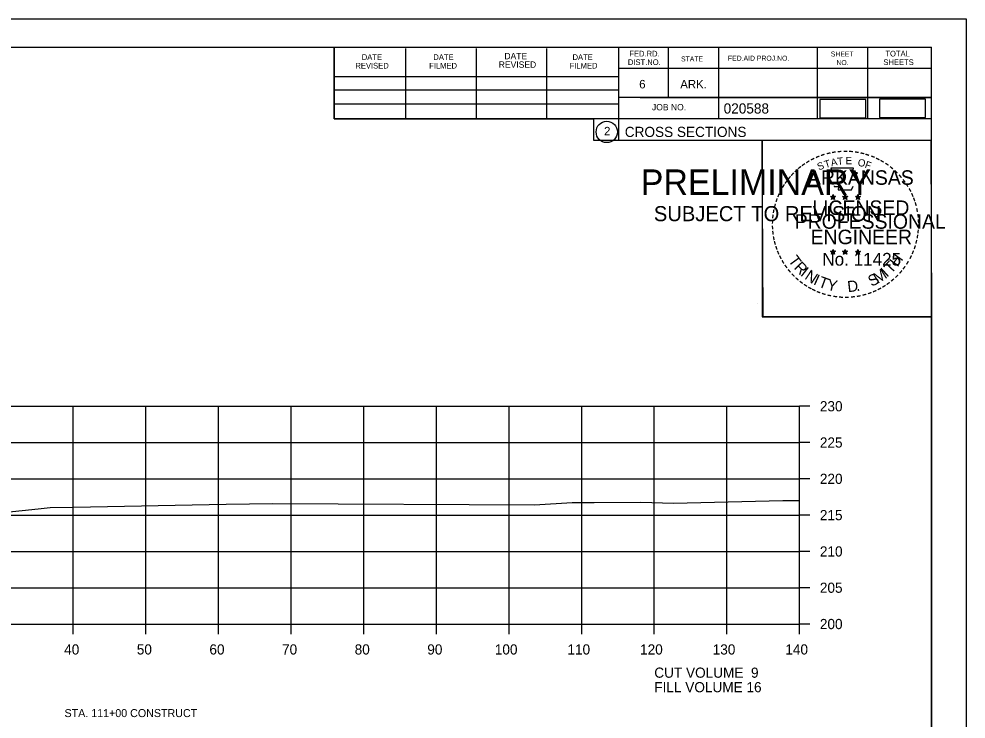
# Model space of a CAD drawing. Extents: x 1368968 to 1369915, y 377395 to 380381.
# Drawn here: x 1369784.3 to 1369914.7, y 377511.6 to 377608 of the extents above; entities that cross this region are included whole.
import ezdxf

# ---------------------------------------------------------------- set-up
doc = ezdxf.new("R2010")
doc.units = 0
for name, color, linetype in [('Default', 7, 'Continuous'), ('S_BREAKLINE_ANNOT', 7, 'Continuous'), ('S_BRIDGE', 7, 'Continuous'), ('S_BRIDGE_ANNOT', 7, 'Continuous'), ('S_BUILDING_ANNOT', 7, 'Continuous'), ('S_CAL_CORNER', 7, 'Continuous'), ('S_CTL_TABLE', 7, 'Continuous'), ('S_DITCHLINE_ANNOT', 7, 'Continuous'), ('S_DROP_INLET', 7, 'Continuous')]:
    doc.layers.add(name, color=color, linetype=linetype)

msp = doc.modelspace()

# ---------------------------------------------------------------- linework, layer by layer
at = {"layer": 'Default'}
for points in [[(1369894.57, 377594.42), (1369900.91, 377594.42), (1369900.91, 377596.94), (1369894.57, 377596.94)], [(1369902.8, 377594.46), (1369909.14, 377594.46), (1369909.14, 377596.98), (1369902.8, 377596.98)]]:
    msp.add_lwpolyline(points, close=True, dxfattribs=at)
at = {"layer": 'S_BREAKLINE_ANNOT'}
for p, q in [((1369891.78, 377524.68), (1369891.78, 377554.68)), ((1369893.18, 377554.68), (1369891.78, 377554.68)), ((1369893.18, 377549.68), (1369891.78, 377549.68)), ((1369893.18, 377544.68), (1369891.78, 377544.68)), ((1369893.18, 377539.68), (1369891.78, 377539.68)), ((1369893.18, 377534.68), (1369891.78, 377534.68)), ((1369893.18, 377529.68), (1369891.78, 377529.68)), ((1369611.78, 377524.68), (1369891.78, 377524.68)), ((1369791.78, 377523.28), (1369791.78, 377524.68)), ((1369801.78, 377523.28), (1369801.78, 377524.68)), ((1369811.78, 377523.28), (1369811.78, 377524.68)), ((1369821.78, 377523.28), (1369821.78, 377524.68)), ((1369831.78, 377523.28), (1369831.78, 377524.68)), ((1369841.78, 377523.28), (1369841.78, 377524.68)), ((1369851.78, 377523.28), (1369851.78, 377524.68)), ((1369861.78, 377523.28), (1369861.78, 377524.68)), ((1369871.78, 377523.28), (1369871.78, 377524.68)), ((1369881.78, 377523.28), (1369881.78, 377524.68)), ((1369891.78, 377523.28), (1369891.78, 377524.68)), ((1369893.18, 377524.68), (1369891.78, 377524.68))]:
    msp.add_line(p, q, dxfattribs=at)
at = {"layer": 'S_BRIDGE_ANNOT'}
for p, q in [((1369593.78, 377604.14), (1369909.96, 377604.14)), ((1369827.7, 377594.26), (1369827.7, 377604.14)), ((1369837.56, 377594.26), (1369837.56, 377603.94)), ((1369847.32, 377594.26), (1369847.32, 377603.94)), ((1369857, 377594.26), (1369857, 377603.94)), ((1369866.86, 377604.14), (1369866.86, 377591.34)), ((1369873.7, 377604.14), (1369873.7, 377597.2)), ((1369880.64, 377604.14), (1369880.64, 377594.26)), ((1369894.22, 377604.14), (1369894.22, 377594.26)), ((1369901.16, 377604.14), (1369901.16, 377594.26)), ((1369909.96, 377398.68), (1369909.96, 377604.14)), ((1369909.96, 377601.22), (1369909.96, 377601.22)), ((1369827.7, 377600.12), (1369866.86, 377600.12)), ((1369909.96, 377601.2), (1369866.86, 377601.2)), ((1369827.7, 377598.26), (1369866.86, 377598.26)), ((1369827.7, 377594.26), (1369827.7, 377596.32)), ((1369827.7, 377596.32), (1369866.86, 377596.32)), ((1369909.96, 377597.2), (1369866.86, 377597.2)), ((1369869.82, 377597.2), (1369909.96, 377597.2)), ((1369909.96, 377594.26), (1369827.7, 377594.26)), ((1369866.86, 377591.34), (1369909.96, 377591.34))]:
    msp.add_line(p, q, dxfattribs=at)
msp.add_circle((1369865.24, 377592.47), 1.47, dxfattribs=at)
at = {"layer": 'S_BUILDING_ANNOT'}
for p, q in [((1369896.04, 377583.59), (1369896.39, 377583.48)), ((1369896.04, 377583.59), (1369896.29, 377583.55)), ((1369896.04, 377583.59), (1369896.28, 377583.47)), ((1369896.17, 377583.18), (1369896.39, 377583.48)), ((1369896.17, 377583.18), (1369896.3, 377583.43)), ((1369896.17, 377583.18), (1369896.39, 377583.4)), ((1369896.39, 377583.85), (1369896.35, 377583.59)), ((1369896.39, 377583.48), (1369896.39, 377583.85)), ((1369896.39, 377583.85), (1369896.44, 377583.6)), ((1369896.74, 377583.59), (1369896.39, 377583.48)), ((1369896.6, 377583.18), (1369896.39, 377583.48)), ((1369896.6, 377583.18), (1369896.39, 377583.4)), ((1369896.74, 377583.59), (1369896.45, 377583.54)), ((1369896.6, 377583.18), (1369896.47, 377583.48)), ((1369896.74, 377583.59), (1369896.53, 377583.49)), ((1369897.71, 377583.59), (1369898.06, 377583.48)), ((1369897.71, 377583.59), (1369897.96, 377583.55)), ((1369897.71, 377583.59), (1369897.95, 377583.47)), ((1369897.84, 377583.18), (1369898.06, 377583.48)), ((1369897.84, 377583.18), (1369897.97, 377583.43)), ((1369897.84, 377583.18), (1369898.06, 377583.4)), ((1369898.06, 377583.85), (1369898.02, 377583.59)), ((1369898.06, 377583.48), (1369898.06, 377583.85)), ((1369898.06, 377583.85), (1369898.11, 377583.6)), ((1369898.41, 377583.59), (1369898.06, 377583.48)), ((1369898.27, 377583.18), (1369898.06, 377583.48)), ((1369898.27, 377583.18), (1369898.06, 377583.4)), ((1369898.41, 377583.59), (1369898.12, 377583.54)), ((1369898.27, 377583.18), (1369898.14, 377583.48)), ((1369898.41, 377583.59), (1369898.2, 377583.49)), ((1369899.48, 377583.58), (1369899.82, 377583.47)), ((1369899.48, 377583.58), (1369899.73, 377583.54)), ((1369899.48, 377583.58), (1369899.71, 377583.46)), ((1369899.61, 377583.17), (1369899.82, 377583.47)), ((1369899.61, 377583.17), (1369899.73, 377583.42)), ((1369899.61, 377583.17), (1369899.82, 377583.39)), ((1369899.82, 377583.83), (1369899.78, 377583.58)), ((1369899.82, 377583.47), (1369899.82, 377583.83)), ((1369899.82, 377583.83), (1369899.87, 377583.58)), ((1369900.17, 377583.58), (1369899.82, 377583.47)), ((1369900.04, 377583.17), (1369899.82, 377583.47)), ((1369900.04, 377583.17), (1369899.82, 377583.39)), ((1369900.17, 377583.58), (1369899.89, 377583.53)), ((1369900.04, 377583.17), (1369899.9, 377583.46)), ((1369900.17, 377583.58), (1369899.97, 377583.48)), ((1369896.04, 377576.02), (1369896.39, 377575.91)), ((1369896.04, 377576.02), (1369896.29, 377575.97)), ((1369896.04, 377576.02), (1369896.27, 377575.9)), ((1369896.17, 377575.61), (1369896.39, 377575.91)), ((1369896.17, 377575.61), (1369896.3, 377575.86)), ((1369896.17, 377575.61), (1369896.38, 377575.83)), ((1369896.39, 377576.27), (1369896.35, 377576.02)), ((1369896.6, 377575.61), (1369896.38, 377575.83)), ((1369896.39, 377575.91), (1369896.39, 377576.27)), ((1369896.39, 377576.27), (1369896.44, 377576.02)), ((1369896.73, 377576.02), (1369896.39, 377575.91)), ((1369896.6, 377575.61), (1369896.39, 377575.91)), ((1369896.73, 377576.02), (1369896.45, 377575.97)), ((1369896.6, 377575.61), (1369896.46, 377575.9)), ((1369896.73, 377576.02), (1369896.53, 377575.92)), ((1369897.71, 377576.02), (1369898.06, 377575.91)), ((1369897.71, 377576.02), (1369897.96, 377575.97)), ((1369897.71, 377576.02), (1369897.94, 377575.9)), ((1369897.84, 377575.61), (1369898.06, 377575.91)), ((1369897.84, 377575.61), (1369897.97, 377575.86)), ((1369897.84, 377575.61), (1369898.05, 377575.83)), ((1369898.06, 377576.27), (1369898.01, 377576.02)), ((1369898.27, 377575.61), (1369898.05, 377575.83)), ((1369898.06, 377575.91), (1369898.06, 377576.27)), ((1369898.06, 377576.27), (1369898.1, 377576.02)), ((1369898.4, 377576.02), (1369898.06, 377575.91)), ((1369898.27, 377575.61), (1369898.06, 377575.91)), ((1369898.4, 377576.02), (1369898.12, 377575.97)), ((1369898.27, 377575.61), (1369898.13, 377575.9)), ((1369898.4, 377576.02), (1369898.2, 377575.92)), ((1369899.47, 377576.01), (1369899.82, 377575.9)), ((1369899.47, 377576.01), (1369899.73, 377575.96)), ((1369899.47, 377576.01), (1369899.71, 377575.89)), ((1369899.61, 377575.6), (1369899.82, 377575.9)), ((1369899.61, 377575.6), (1369899.73, 377575.85)), ((1369899.61, 377575.6), (1369899.82, 377575.82)), ((1369899.82, 377576.26), (1369899.78, 377576.01)), ((1369899.82, 377575.9), (1369899.82, 377576.26)), ((1369899.82, 377576.26), (1369899.87, 377576.01)), ((1369900.17, 377576.01), (1369899.82, 377575.9)), ((1369900.04, 377575.6), (1369899.82, 377575.9)), ((1369900.04, 377575.6), (1369899.82, 377575.82)), ((1369900.17, 377576.01), (1369899.88, 377575.96)), ((1369900.04, 377575.6), (1369899.9, 377575.89)), ((1369900.17, 377576.01), (1369899.97, 377575.91))]:
    msp.add_line(p, q, dxfattribs=at)
for points in [[(1369896.08, 377587.47), (1369896.35, 377586.64)], [(1369899.59, 377586.55), (1369899.74, 377586.83), (1369899.05, 377586.81), (1369899.2, 377587.47), (1369896.08, 377587.47)], [(1369896.57, 377585.05), (1369896.57, 377584.96), (1369897.14, 377584.94), (1369897.08, 377584.47), (1369898.95, 377584.47), (1369899.15, 377585)], [(1369896.39, 377583.85), (1369896.6, 377583.18), (1369896.04, 377583.59), (1369896.74, 377583.59), (1369896.17, 377583.18), (1369896.39, 377583.85)], [(1369898.06, 377583.85), (1369898.27, 377583.18), (1369897.71, 377583.59), (1369898.41, 377583.59), (1369897.84, 377583.18), (1369898.06, 377583.85)], [(1369899.82, 377583.83), (1369900.04, 377583.17), (1369899.48, 377583.58), (1369900.17, 377583.58), (1369899.61, 377583.17), (1369899.82, 377583.83)], [(1369896.39, 377576.27), (1369896.6, 377575.61), (1369896.04, 377576.02), (1369896.73, 377576.02), (1369896.17, 377575.61), (1369896.39, 377576.27)], [(1369898.06, 377576.27), (1369898.27, 377575.61), (1369897.71, 377576.02), (1369898.4, 377576.02), (1369897.84, 377575.61), (1369898.06, 377576.27)], [(1369899.82, 377576.26), (1369900.04, 377575.6), (1369899.47, 377576.01), (1369900.17, 377576.01), (1369899.61, 377575.6), (1369899.82, 377576.26)]]:
    msp.add_lwpolyline(points, dxfattribs=at)
for centre, radius in [((1369896.39, 377583.48), 0.172), ((1369896.39, 377583.48), 0.145), ((1369896.39, 377583.48), 0.116), ((1369896.39, 377583.48), 0.0991), ((1369896.39, 377583.48), 0.0747), ((1369896.39, 377583.48), 0.0495), ((1369896.39, 377583.48), 0.0296), ((1369898.06, 377583.48), 0.172), ((1369898.06, 377583.48), 0.145), ((1369898.06, 377583.48), 0.116), ((1369898.06, 377583.48), 0.0991), ((1369898.06, 377583.48), 0.0747), ((1369898.06, 377583.48), 0.0495), ((1369898.06, 377583.48), 0.0296), ((1369899.82, 377583.47), 0.172), ((1369899.82, 377583.47), 0.145), ((1369899.82, 377583.47), 0.116), ((1369899.82, 377583.47), 0.0991), ((1369899.82, 377583.47), 0.0747), ((1369899.82, 377583.47), 0.0495), ((1369899.82, 377583.47), 0.0296), ((1369896.39, 377575.91), 0.172), ((1369896.39, 377575.91), 0.145), ((1369896.39, 377575.91), 0.116), ((1369896.39, 377575.91), 0.0991), ((1369896.39, 377575.91), 0.0747), ((1369896.39, 377575.91), 0.0495), ((1369896.39, 377575.91), 0.0296), ((1369898.05, 377575.91), 0.172), ((1369898.05, 377575.91), 0.145), ((1369898.05, 377575.91), 0.116), ((1369898.05, 377575.91), 0.0991), ((1369898.05, 377575.91), 0.0747), ((1369898.05, 377575.91), 0.0495), ((1369898.05, 377575.91), 0.0296), ((1369899.82, 377575.9), 0.172), ((1369899.82, 377575.9), 0.145), ((1369899.82, 377575.9), 0.116), ((1369899.82, 377575.9), 0.0991), ((1369899.82, 377575.9), 0.0747), ((1369899.82, 377575.9), 0.0495), ((1369899.82, 377575.9), 0.0296)]:
    msp.add_circle(centre, radius, dxfattribs=at)
at = {"layer": 'S_CTL_TABLE'}
msp.add_lwpolyline([(1369779.39, 377539.78), (1369786.96, 377540.54), (1369788.58, 377540.73), (1369791.79, 377540.79), (1369812.81, 377541.17), (1369819.27, 377541.29), (1369855.29, 377541.1), (1369860.49, 377541.4), (1369862.26, 377541.41), (1369863.51, 377541.41), (1369869.91, 377541.46), (1369874.44, 377541.33), (1369889.5, 377541.69), (1369891.78, 377541.7)], dxfattribs=at)
at = {"layer": 'S_DITCHLINE_ANNOT'}
for p, q in [((1369611.78, 377554.68), (1369891.78, 377554.68)), ((1369791.78, 377524.68), (1369791.78, 377554.68)), ((1369801.78, 377524.68), (1369801.78, 377554.68)), ((1369811.78, 377524.68), (1369811.78, 377554.68)), ((1369821.78, 377524.68), (1369821.78, 377554.68)), ((1369831.78, 377524.68), (1369831.78, 377554.68)), ((1369841.78, 377524.68), (1369841.78, 377554.68)), ((1369851.78, 377524.68), (1369851.78, 377554.68)), ((1369861.78, 377524.68), (1369861.78, 377554.68)), ((1369871.78, 377524.68), (1369871.78, 377554.68)), ((1369881.78, 377524.68), (1369881.78, 377554.68)), ((1369891.78, 377524.68), (1369891.78, 377554.68)), ((1369611.78, 377549.68), (1369891.78, 377549.68)), ((1369611.78, 377544.68), (1369891.78, 377544.68)), ((1369611.78, 377539.68), (1369891.78, 377539.68)), ((1369611.78, 377534.68), (1369891.78, 377534.68)), ((1369611.78, 377529.68), (1369891.78, 377529.68)), ((1369611.78, 377524.68), (1369891.78, 377524.68))]:
    msp.add_line(p, q, dxfattribs=at)
at = {"layer": 'S_DROP_INLET'}
for p, q in [((1369581.38, 377608.03), (1369914.71, 377608.03)), ((1369885.99, 377568.88), (1369885.99, 377568.88))]:
    msp.add_line(p, q, dxfattribs=at)
for points in [[(1369581.37, 377608.03), (1369914.71, 377608.03), (1369914.71, 377394.69), (1369581.37, 377394.69)], [(1369827.7, 377604.14), (1369827.7, 377594.26), (1369863.43, 377594.26), (1369863.43, 377591.34), (1369886.63, 377591.34), (1369886.63, 377567), (1369909.96, 377567), (1369909.96, 377398.68), (1369593.78, 377398.68), (1369593.78, 377604.14)], [(1369886.63, 377591.34), (1369909.84, 377591.34), (1369909.96, 377567), (1369886.75, 377567)]]:
    msp.add_lwpolyline(points, close=True, dxfattribs=at)

# ---------------------------------------------------------------- texts
at = {"layer": 'Default'}
msp.add_text('STA. 111+00 CONSTRUCT', height=1.1, dxfattribs=at).set_placement((1369790.57, 377511.86))
at = {"layer": 'S_BRIDGE'}
for s, p in [('230', (1369894.58, 377553.98)), ('225', (1369894.58, 377548.98)), ('220', (1369894.58, 377543.98)), ('215', (1369894.58, 377538.98)), ('210', (1369894.58, 377533.98)), ('205', (1369894.58, 377528.98)), ('200', (1369894.58, 377523.98)), ('40', (1369790.52, 377520.48)), ('50', (1369800.52, 377520.48)), ('60', (1369810.52, 377520.48)), ('70', (1369820.52, 377520.48)), ('80', (1369830.52, 377520.48)), ('90', (1369840.52, 377520.48)), ('100', (1369849.82, 377520.48)), ('110', (1369859.82, 377520.48)), ('120', (1369869.82, 377520.48)), ('130', (1369879.82, 377520.48)), ('140', (1369889.82, 377520.48)), ('CUT VOLUME  9', (1369871.78, 377517.28)), ('FILL VOLUME 16', (1369871.78, 377515.28))]:
    msp.add_text(s, height=1.4, dxfattribs=at).set_placement(p)
at = {"layer": 'S_BRIDGE_ANNOT'}
for s, height, p in [('DATE', 0.782, (1369831.5, 377602.38)), ('DATE', 0.782, (1369841.36, 377602.38)), ('DATE', 0.879, (1369851.14, 377602.48)), ('DATE', 0.782, (1369860.52, 377602.38)), ('FED.RD.', 0.782, (1369868.34, 377602.86)), ('STATE', 0.684, (1369875.46, 377602.18)), ('FED.AID PROJ.NO.', 0.684, (1369881.92, 377602.28)), ('SHEET', 0.684, (1369896.08, 377602.86)), ('TOTAL', 0.782, (1369903.6, 377602.86)), ('REVISED', 0.782, (1369830.62, 377601.2)), ('FILMED', 0.782, (1369840.78, 377601.2)), ('REVISED', 0.879, (1369850.36, 377601.3)), ('FILMED', 0.782, (1369860.12, 377601.2)), ('DIST.NO.', 0.782, (1369868.14, 377601.68)), ('NO.', 0.684, (1369896.86, 377601.68)), ('SHEETS', 0.782, (1369903.32, 377601.68)), ('6', 1.17, (1369869.7, 377598.46)), ('ARK.', 1.172, (1369875.36, 377598.46)), ('JOB NO.', 0.879, (1369871.46, 377595.44)), ('020588', 1.4, (1369881.33, 377595)), ('2', 1.17, (1369864.86, 377591.99)), ('CROSS SECTIONS', 1.4, (1369867.72, 377591.77))]:
    msp.add_text(s, height=height, rotation=360, dxfattribs=at).set_placement(p)
at = {"layer": 'S_BUILDING_ANNOT'}
for s, height, rotation, p in [('-', 1.6, 13.6301, (1369895.58, 377588.84)), ('-', 1.6, 10.2193, (1369896.26, 377589)), ('-', 1.6, 5.8968, (1369896.99, 377589.11)), ('-', 1.6, 0.1862, (1369897.76, 377589.18)), ('-', 1.6, 357.743, (1369898.48, 377589.17)), ('-', 1.6, 352.1617, (1369899.23, 377589.11)), ('-', 1.6, 347.2049, (1369899.95, 377589)), ('-', 1.6, 342.3362, (1369900.58, 377588.84)), ('-', 1.6, 36.2317, (1369892.39, 377587.25)), ('-', 1.6, 34.0636, (1369892.97, 377587.64)), ('-', 1.6, 28.7918, (1369893.56, 377588.01)), ('-', 1.6, 24.3072, (1369894.2, 377588.33)), ('S', 1, 21.594, (1369894.44, 377587.15)), ('-', 1.6, 19.1761, (1369894.83, 377588.6)), ('T', 1, 16.4036, (1369895.35, 377587.48)), ('A', 1, 11.2132, (1369896.18, 377587.73)), ('T', 1, 6.0228, (1369897.03, 377587.9)), ('E', 1, 0.8323, (1369898.13, 377588.01)), ('O', 1, 350.4515, (1369899.74, 377587.8)), ('F', 1, 340.0707, (1369900.69, 377587.57)), ('-', 1.6, 337.8551, (1369901.32, 377588.62)), ('-', 1.6, 334.1211, (1369901.95, 377588.35)), ('-', 1.6, 329.6409, (1369902.53, 377588.07)), ('-', 1.6, 325.8627, (1369903.17, 377587.71)), ('-', 1.6, 48.423, (1369891.03, 377585.97)), ('-', 1.6, 42.9622, (1369891.48, 377586.45)), ('-', 1.6, 38.9507, (1369891.91, 377586.87)), ('ARKANSAS', 2, 360, (1369892.94, 377585.18)), ('-', 1.6, 320.5297, (1369903.78, 377587.28)), ('-', 1.6, 315.5786, (1369904.38, 377586.79)), ('-', 1.6, 54.2325, (1369890.22, 377584.92)), ('-', 1.6, 50.6142, (1369890.63, 377585.49)), ('-', 1.6, 309.8797, (1369904.95, 377586.24)), ('-', 1.6, 306.6522, (1369905.47, 377585.64)), ('-', 1.6, 62.8713, (1369889.58, 377583.78)), ('-', 1.6, 58.0706, (1369889.89, 377584.39)), ('-', 1.4, 303.6753, (1369905.96, 377585.07)), ('-', 1.6, 299.6684, (1369906.28, 377584.47)), ('-', 1.6, 72.3945, (1369889.1, 377582.54)), ('-', 1.6, 67.7743, (1369889.32, 377583.17)), ('LICENSED', 2, 360, (1369893.53, 377581.03)), ('DWB', 0.01, 360, (1369896.38, 377583.48)), ('DWB', 0.01, 360, (1369898.05, 377583.48)), ('DWB', 0.01, 360, (1369899.81, 377583.47)), ('-', 1.6, 294.6628, (1369906.6, 377583.85)), ('-', 1.6, 290.5728, (1369906.86, 377583.28)), ('-', 1.6, 81.2013, (1369888.77, 377581.11)), ('-', 1.6, 75.461, (1369888.9, 377581.82)), ('-', 1.6, 285.1233, (1369907.09, 377582.7)), ('-', 1.6, 280.5493, (1369907.29, 377581.95)), ('-', 1.6, 89.0622, (1369888.67, 377579.72)), ('-', 1.6, 85.1863, (1369888.69, 377580.42)), ('PROFESSIONAL', 2, 360, (1369891.11, 377579.13)), ('-', 1.6, 276.5962, (1369907.45, 377581.19)), ('-', 1.6, 274.3301, (1369907.51, 377580.46)), ('-', 1.6, 94.1959, (1369888.7, 377578.99)), ('-', 1.6, 269.9407, (1369907.55, 377579.83)), ('-', 1.6, 98.9479, (1369888.78, 377578.33)), ('-', 1.6, 101.7149, (1369888.91, 377577.59)), ('ENGINEER', 2, 360, (1369893.3, 377577)), ('-', 1.6, 260.9953, (1369907.46, 377578.51)), ('-', 1.6, 263.5172, (1369907.53, 377579.17)), ('-', 1.6, 105.4578, (1369889.07, 377577)), ('-', 1.6, 109.0874, (1369889.29, 377576.37)), ('-', 1.6, 252.8681, (1369907.17, 377577.11)), ('-', 1.6, 255.7626, (1369907.35, 377577.83)), ('-', 1.6, 114.0643, (1369889.54, 377575.77)), ('-', 1.6, 115.7289, (1369889.85, 377575.15)), ('T', 1.54, 306.0406, (1369890.15, 377574.75)), ('No. 11425', 1.757, 360, (1369894.92, 377574.05)), ('DWB', 0.01, 360, (1369896.37, 377575.9)), ('DWB', 0.01, 360, (1369898.04, 377575.9)), ('DWB', 0.01, 360, (1369899.81, 377575.89)), ('H', 1.54, 54.6088, (1369905.27, 377573.78)), ('-', 1.6, 244.6197, (1369906.68, 377575.81)), ('-', 1.6, 247.8887, (1369906.94, 377576.44)), ('-', 1.6, 120.4471, (1369890.2, 377574.57)), ('-', 1.6, 125.8934, (1369890.61, 377574.01)), ('R', 1.54, 314.005, (1369890.91, 377573.7)), ('I', 1.54, 321.9694, (1369891.81, 377572.77)), ('T', 1.54, 46.6444, (1369904.38, 377572.84)), ('-', 1.6, 233.8452, (1369905.89, 377574.41)), ('-', 1.6, 239.0712, (1369906.29, 377575.06)), ('-', 1.6, 130.7181, (1369891.07, 377573.46)), ('-', 1.6, 134.2238, (1369891.59, 377572.91)), ('N', 1.54, 326.5002, (1369892.38, 377572.29)), ('I', 1.54, 335.3603, (1369893.58, 377571.51)), ('T', 1.54, 339.8912, (1369894.25, 377571.18)), ('S', 1.54, 26.9312, (1369901.69, 377571.11)), ('M', 1.54, 32.6563, (1369902.53, 377571.51)), ('I', 1.54, 42.1136, (1369903.81, 377572.36)), ('-', 1.6, 225.7653, (1369904.98, 377573.28)), ('-', 1.6, 231.2538, (1369905.46, 377573.84)), ('-', 1.6, 138.9338, (1369892.11, 377572.45)), ('-', 1.6, 144.6463, (1369892.67, 377572.04)), ('-', 1.6, 148.0898, (1369893.23, 377571.67)), ('Y', 1.54, 347.8556, (1369895.46, 377570.74)), ('D', 1.54, 6.3969, (1369898.45, 377570.38)), ('-', 1.6, 212.2491, (1369903.37, 377571.91)), ('-', 1.6, 215.7363, (1369903.91, 377572.3)), ('-', 1.6, 221.0851, (1369904.45, 377572.77)), ('-', 1.6, 151.5704, (1369893.81, 377571.34)), ('-', 1.6, 154.6002, (1369894.33, 377571.1)), ('-', 1.6, 158.5612, (1369894.95, 377570.84)), ('-', 1.6, 162.7983, (1369895.64, 377570.63)), ('-', 1.6, 167.5555, (1369896.36, 377570.47)), ('-', 1.6, 191.2858, (1369900.16, 377570.53)), ('.', 1.54, 13.7642, (1369899.64, 377570.51)), ('-', 1.6, 195.4743, (1369900.89, 377570.73)), ('-', 1.6, 200.7184, (1369901.57, 377570.97)), ('-', 1.6, 204.2516, (1369902.19, 377571.24)), ('-', 1.6, 207.3568, (1369902.81, 377571.56)), ('-', 1.6, 173.1155, (1369897.13, 377570.36)), ('-', 1.6, 176.5183, (1369897.88, 377570.3)), ('-', 1.6, 181.5918, (1369898.62, 377570.32)), ('-', 1.6, 185.8167, (1369899.43, 377570.4))]:
    msp.add_text(s, height=height, rotation=rotation, dxfattribs=at).set_placement(p)
at = {"layer": 'S_CAL_CORNER'}
for s, height, p in [('PRELIMINARY', 3.5, (1369869.91, 377583.8)), ('DWB', 0.01, (1369870.65, 377585.65)), ('SUBJECT TO REVISION', 2.0751, (1369871.72, 377580.17))]:
    msp.add_text(s, height=height, rotation=360, dxfattribs=at).set_placement(p)

doc.saveas('drawing.dxf')
